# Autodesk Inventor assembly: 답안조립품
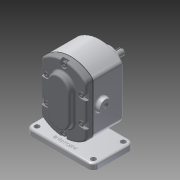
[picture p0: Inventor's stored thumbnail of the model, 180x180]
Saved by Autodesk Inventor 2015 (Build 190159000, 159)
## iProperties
Created: 2019-03
Part Number: 답안조립품
Document SubType Name: Assembly
Designer: now
Author: now
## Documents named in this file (11)
- C:\Users\now\Desktop\490307V1043\답안조립품.iam
- C:\Users\now\Desktop\490307V1043\개스킷.ipt
- C:\Users\now\Desktop\490307V1043\메인축.ipt
- C:\Users\now\Desktop\490307V1043\베어링부시.ipt
- C:\Users\now\Desktop\490307V1043\본체.ipt
- C:\Users\now\Desktop\490307V1043\볼트 M5.ipt
- C:\Users\now\Desktop\490307V1043\서브축.ipt
- C:\Users\now\Desktop\490307V1043\스퍼기어.ipt
- C:\Users\now\Desktop\490307V1043\오일 실 16 28 7.ipt
- C:\Users\now\Desktop\490307V1043\커버.ipt
- C:\Users\now\Desktop\490307V1043\키 6 x 6 x 18.ipt
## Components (1 placed, 1 different names)
1. 개스킷:1
